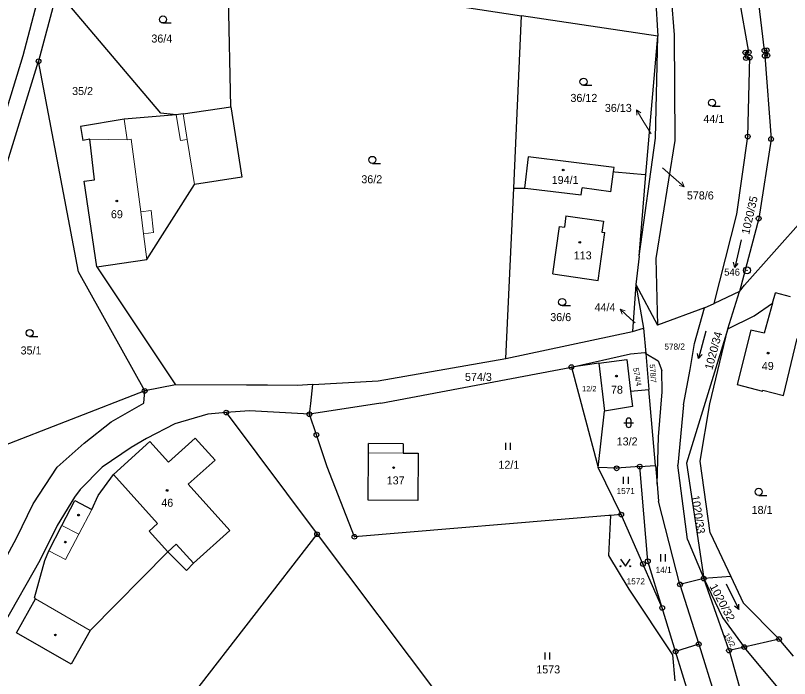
# Model space of a CAD drawing. Extents: x -601131 to -597152, y -1058536 to -1055911.
# Drawn here: x -599584.4 to -599420.5, y -1057555.3 to -1057414.9 of the extents above; entities that cross this region are included whole.
import ezdxf
from ezdxf.enums import TextEntityAlignment as Align

# ---------------------------------------------------------------- set-up
doc = ezdxf.new("R2010")
doc.units = 0
doc.header["$LTSCALE"] = 0.68
for name, color, linetype, lineweight in [('1', 7, 'Continuous', 25), ('3', 7, 'Continuous', 25), ('4', 7, 'Continuous', 13), ('5', 7, 'Continuous', 25), ('7', 7, 'Continuous', 13), ('8', 7, 'Continuous', 25)]:
    doc.layers.add(name, color=color, linetype=linetype, lineweight=lineweight)
doc.layers.add('2', color=7, linetype='Continuous')

msp = doc.modelspace()

# ---------------------------------------------------------------- linework, layer by layer
at = {"layer": '1'}
for p, q in [((-599429.13, -1057422.65), (-599435.94, -1057383.82)), ((-599576.56, -1057399.07), (-599582.83, -1057423.44)), ((-599425.81, -1057422.29), (-599427.99, -1057403.92)), ((-599539.45, -1057405.43), (-599477.25, -1057414.93)), ((-599538.83, -1057434.23), (-599539.45, -1057405.43)), ((-599575.56, -1057409.62), (-599579.52, -1057424.57)), ((-599445.63, -1057410.37), (-599444.9, -1057418.96)), ((-599553.62, -1057435.58), (-599574.11, -1057411.33)), ((-599448.9, -1057410.94), (-599448.41, -1057419.24)), ((-599478.88, -1057451.46), (-599477.25, -1057414.93)), ((-599448.41, -1057419.24), (-599477.25, -1057414.93)), ((-599444.9, -1057418.96), (-599444.76, -1057441.37)), ((-599450.89, -1057448.55), (-599448.41, -1057419.24)), ((-599448.85, -1057440.85), (-599448.41, -1057419.24)), ((-599425.81, -1057422.29), (-599425.32, -1057422.24)), ((-599425.32, -1057422.24), (-599425.2, -1057423.37)), ((-599582.83, -1057423.44), (-599589.35, -1057444.57)), ((-599429.73, -1057423.88), (-599428.91, -1057423.79)), ((-599429.33, -1057440.52), (-599428.91, -1057423.79)), ((-599425.2, -1057423.37), (-599425.73, -1057423.43)), ((-599425.73, -1057423.43), (-599424.4, -1057441.04)), ((-599586.09, -1057445.85), (-599579.52, -1057424.57)), ((-599571.05, -1057469.19), (-599579.52, -1057424.57)), ((-599548.9, -1057435.71), (-599538.83, -1057434.23)), ((-599538.83, -1057434.23), (-599536.5, -1057449.14)), ((-599561.39, -1057436.83), (-599570.64, -1057438.38)), ((-599550.36, -1057435.92), (-599561.39, -1057436.83)), ((-599550.36, -1057435.92), (-599553.62, -1057435.58)), ((-599548.9, -1057435.71), (-599550.36, -1057435.92)), ((-599570.64, -1057438.38), (-599570.15, -1057441.32)), ((-599568.65, -1057441.07), (-599570.15, -1057441.32)), ((-599567.7, -1057449.67), (-599568.65, -1057441.07)), ((-599452.36, -1057465.85), (-599448.85, -1057440.85)), ((-599444.76, -1057441.37), (-599448.83, -1057466.34)), ((-599431.65, -1057456.93), (-599429.33, -1057440.52)), ((-599424.4, -1057441.04), (-599427.03, -1057457.88)), ((-599475.87, -1057444.81), (-599476.59, -1057451.42)), ((-599457.64, -1057447.06), (-599475.87, -1057444.81)), ((-599458.34, -1057452.25), (-599457.76, -1057447.95)), ((-599457.76, -1057447.95), (-599457.64, -1057447.06)), ((-599457.76, -1057447.95), (-599457.48, -1057447.97)), ((-599457.48, -1057447.97), (-599451.11, -1057448.53)), ((-599451.11, -1057448.53), (-599450.89, -1057448.55)), ((-599569.89, -1057450), (-599567.7, -1057449.67)), ((-599567.16, -1057468.15), (-599569.89, -1057450)), ((-599536.5, -1057449.14), (-599546.51, -1057450.66)), ((-599452.36, -1057465.85), (-599450.89, -1057448.55)), ((-599556.6, -1057466.57), (-599546.51, -1057450.66)), ((-599480.54, -1057487.54), (-599478.88, -1057451.46)), ((-599478.88, -1057451.46), (-599476.59, -1057451.42)), ((-599476.59, -1057451.42), (-599476.45, -1057451.44)), ((-599476.45, -1057451.44), (-599464.64, -1057452.84)), ((-599464.64, -1057452.84), (-599464.44, -1057451.39)), ((-599458.34, -1057452.25), (-599464.44, -1057451.39)), ((-599467.88, -1057457.31), (-599468.17, -1057459.69)), ((-599467.88, -1057457.31), (-599459.91, -1057458.46)), ((-599436.45, -1057475.86), (-599431.65, -1057456.93)), ((-599427.03, -1057457.88), (-599431.06, -1057473.32)), ((-599430.01, -1057472.01), (-599417.49, -1057457.87)), ((-599470.62, -1057469.6), (-599469.2, -1057459.56)), ((-599469.2, -1057459.56), (-599468.17, -1057459.69)), ((-599459.91, -1057458.46), (-599460.23, -1057460.78)), ((-599461.02, -1057471.05), (-599459.64, -1057460.86)), ((-599460.23, -1057460.78), (-599459.64, -1057460.86)), ((-599448.83, -1057466.34), (-599448.42, -1057480.45)), ((-599567.16, -1057468.15), (-599556.6, -1057466.57)), ((-599567.16, -1057468.15), (-599550.49, -1057493.11)), ((-599557.05, -1057494.41), (-599571.05, -1057469.19)), ((-599470.62, -1057469.6), (-599461.02, -1057471.05)), ((-599453.06, -1057471.87), (-599453.74, -1057481.84)), ((-599453.06, -1057471.87), (-599451.39, -1057481.12)), ((-599431.06, -1057473.32), (-599430.01, -1057472.01)), ((-599431.06, -1057473.32), (-599436.45, -1057475.86)), ((-599433.54, -1057481.26), (-599431.06, -1057473.32)), ((-599424.11, -1057475.85), (-599423.48, -1057473.61)), ((-599420.32, -1057474.45), (-599423.48, -1057473.61)), ((-599438.48, -1057476.82), (-599436.45, -1057475.86)), ((-599427.95, -1057478.47), (-599424.11, -1057475.85)), ((-599424.11, -1057475.85), (-599425.87, -1057482.14)), ((-599438.48, -1057476.82), (-599448.42, -1057480.45)), ((-599440.6, -1057484.39), (-599438.48, -1057476.82)), ((-599433.54, -1057481.26), (-599427.95, -1057478.47)), ((-599453.74, -1057481.84), (-599451.39, -1057481.12)), ((-599451.39, -1057481.12), (-599450.93, -1057486.45)), ((-599433.54, -1057481.26), (-599442.33, -1057509.73)), ((-599437.38, -1057497.13), (-599433.54, -1057481.26)), ((-599480.54, -1057487.54), (-599453.74, -1057481.84)), ((-599428.67, -1057481.52), (-599431.56, -1057493.06)), ((-599425.87, -1057482.14), (-599428.67, -1057481.52)), ((-599441.54, -1057489.85), (-599440.6, -1057484.39)), ((-599421.79, -1057495.35), (-599418.87, -1057483.31)), ((-599507.58, -1057492.26), (-599480.54, -1057487.54)), ((-599466.67, -1057489.35), (-599454.15, -1057486.55)), ((-599460.87, -1057488.55), (-599454.95, -1057487.73)), ((-599454.95, -1057487.73), (-599454.15, -1057494.47)), ((-599450.93, -1057486.45), (-599448.33, -1057488.07)), ((-599450.93, -1057486.45), (-599450.28, -1057494.08)), ((-599507.04, -1057497.01), (-599466.67, -1057489.35)), ((-599460.87, -1057488.55), (-599466.67, -1057489.35)), ((-599466.67, -1057489.35), (-599461.02, -1057510.61)), ((-599460.87, -1057488.55), (-599459.71, -1057498.67)), ((-599448.33, -1057488.07), (-599447.53, -1057490.08)), ((-599447.48, -1057494.57), (-599447.53, -1057490.08)), ((-599442.92, -1057497.38), (-599441.54, -1057489.85)), ((-599521.47, -1057493.07), (-599507.58, -1057492.26)), ((-599557.05, -1057494.41), (-599595.76, -1057509.42)), ((-599557.26, -1057497.01), (-599557.05, -1057494.41)), ((-599550.49, -1057493.11), (-599557.05, -1057494.41)), ((-599535.5, -1057493.2), (-599550.49, -1057493.11)), ((-599531.04, -1057493.21), (-599535.5, -1057493.2)), ((-599524.78, -1057493.23), (-599531.04, -1057493.21)), ((-599521.47, -1057493.07), (-599524.78, -1057493.23)), ((-599521.9, -1057497.05), (-599521.47, -1057493.07)), ((-599454.15, -1057494.47), (-599450.28, -1057494.08)), ((-599448.88, -1057510.19), (-599450.28, -1057494.08)), ((-599431.56, -1057493.06), (-599426.19, -1057494.46)), ((-599426.19, -1057494.46), (-599426.15, -1057494.28)), ((-599426.15, -1057494.28), (-599421.79, -1057495.35)), ((-599454.15, -1057494.47), (-599453.76, -1057497.74)), ((-599448.25, -1057504.11), (-599447.48, -1057494.57)), ((-599564.18, -1057500.99), (-599557.26, -1057497.01)), ((-599507.04, -1057497.01), (-599522.15, -1057499.34)), ((-599522.15, -1057499.34), (-599521.9, -1057497.05)), ((-599442.92, -1057497.38), (-599444.18, -1057510.12)), ((-599439.43, -1057509.3), (-599437.38, -1057497.13)), ((-599539.77, -1057498.99), (-599543.66, -1057499.37)), ((-599534.83, -1057498.6), (-599539.77, -1057498.99)), ((-599539.77, -1057498.99), (-599520.55, -1057524.78)), ((-599522.15, -1057499.34), (-599534.83, -1057498.6)), ((-599520.67, -1057503.74), (-599522.15, -1057499.34)), ((-599461.02, -1057510.61), (-599459.71, -1057498.67)), ((-599453.76, -1057497.74), (-599459.71, -1057498.67)), ((-599543.66, -1057499.37), (-599550.67, -1057501.4)), ((-599569.89, -1057505.48), (-599564.18, -1057500.99)), ((-599550.67, -1057501.4), (-599556.64, -1057504.51)), ((-599518.39, -1057510.52), (-599520.67, -1057503.74)), ((-599448.53, -1057514.19), (-599448.25, -1057504.11)), ((-599575.55, -1057510.53), (-599569.89, -1057505.48)), ((-599563.66, -1057512.09), (-599555.97, -1057505.14)), ((-599556.64, -1057504.51), (-599559.92, -1057506.43)), ((-599555.97, -1057505.14), (-599552, -1057509.51)), ((-599552, -1057509.51), (-599546.33, -1057504.4)), ((-599546.33, -1057504.4), (-599542.14, -1057509.05)), ((-599509.68, -1057507.53), (-599509.67, -1057505.53)), ((-599502.28, -1057505.61), (-599509.67, -1057505.53)), ((-599502.28, -1057505.61), (-599502.28, -1057507.57)), ((-599559.92, -1057506.43), (-599566.02, -1057510.55)), ((-599509.71, -1057517.59), (-599509.68, -1057507.53)), ((-599542.14, -1057509.05), (-599547.84, -1057514.18)), ((-599502.28, -1057507.57), (-599499.16, -1057507.57)), ((-599499.16, -1057507.57), (-599499.2, -1057517.63)), ((-599580.69, -1057518.33), (-599575.55, -1057510.53)), ((-599566.02, -1057510.55), (-599570.69, -1057515.28)), ((-599512.64, -1057525.32), (-599518.39, -1057510.52)), ((-599456.13, -1057520.62), (-599461.02, -1057510.61)), ((-599457.11, -1057510.81), (-599461.02, -1057510.61)), ((-599452.21, -1057510.44), (-599457.11, -1057510.81)), ((-599452.21, -1057510.44), (-599448.88, -1057510.19)), ((-599450.5, -1057530.51), (-599452.21, -1057510.44)), ((-599448.88, -1057510.19), (-599448.53, -1057514.19)), ((-599442.11, -1057525.88), (-599444.18, -1057510.12)), ((-599442.33, -1057509.73), (-599438.67, -1057534.18)), ((-599437.27, -1057524.48), (-599439.43, -1057509.3)), ((-599566.93, -1057516.54), (-599563.66, -1057512.09)), ((-599570.69, -1057515.28), (-599571.92, -1057516.93)), ((-599547.84, -1057514.18), (-599539.01, -1057524)), ((-599448.53, -1057514.19), (-599448.22, -1057517.77)), ((-599571.92, -1057516.93), (-599575.59, -1057522.91)), ((-599568.24, -1057519.52), (-599566.93, -1057516.54)), ((-599584.18, -1057525.58), (-599580.69, -1057518.33)), ((-599574.6, -1057522.94), (-599571.84, -1057517.6)), ((-599571.84, -1057517.6), (-599568.24, -1057519.52)), ((-599499.2, -1057517.63), (-599509.71, -1057517.59)), ((-599443.69, -1057535.4), (-599448.22, -1057517.77)), ((-599456.13, -1057520.62), (-599458.43, -1057520.81)), ((-599451.54, -1057531.08), (-599456.13, -1057520.62)), ((-599458.78, -1057520.84), (-599512.64, -1057525.32)), ((-599458.43, -1057520.81), (-599458.8, -1057529.28)), ((-599458.43, -1057520.81), (-599458.78, -1057520.84)), ((-599575.59, -1057522.91), (-599579.25, -1057530.31)), ((-599577.37, -1057528.29), (-599574.6, -1057522.94)), ((-599568.17, -1057586.29), (-599520.55, -1057524.78)), ((-599539.01, -1057524), (-599546.7, -1057530.92)), ((-599520.55, -1057524.78), (-599475.21, -1057585.02)), ((-599437.27, -1057524.48), (-599432.94, -1057533.76)), ((-599592.18, -1057540.3), (-599584.18, -1057525.58)), ((-599442.11, -1057525.88), (-599438.67, -1057534.18)), ((-599578.22, -1057530.31), (-599577.37, -1057528.29)), ((-599552.12, -1057528.49), (-599568.62, -1057545.16)), ((-599548.17, -1057532.47), (-599552.12, -1057528.49)), ((-599579.25, -1057530.31), (-599586.95, -1057543.9)), ((-599580.4, -1057538.26), (-599578.22, -1057530.31)), ((-599458.8, -1057529.28), (-599454.54, -1057536.41)), ((-599546.7, -1057530.92), (-599548.17, -1057532.47)), ((-599447.46, -1057540.37), (-599451.54, -1057531.08)), ((-599447.46, -1057540.37), (-599450.5, -1057530.51)), ((-599432.94, -1057533.76), (-599438.67, -1057534.18)), ((-599432.94, -1057533.76), (-599430.34, -1057539.31)), ((-599441.18, -1057534.8), (-599443.69, -1057535.4)), ((-599443.69, -1057535.4), (-599439.72, -1057548.06)), ((-599438.67, -1057534.18), (-599441.18, -1057534.8)), ((-599438.67, -1057534.18), (-599434.67, -1057542.4)), ((-599433.31, -1057549.41), (-599438.67, -1057534.18)), ((-599454.54, -1057536.41), (-599445.3, -1057550.3)), ((-599584.21, -1057545.64), (-599580.15, -1057538.44)), ((-599580.15, -1057538.44), (-599580.4, -1057538.26)), ((-599430.34, -1057539.31), (-599422.72, -1057547)), ((-599434.67, -1057542.4), (-599430.08, -1057548.68)), ((-599568.62, -1057545.16), (-599572.64, -1057552.3)), ((-599572.64, -1057552.3), (-599584.21, -1057545.64)), ((-599439.72, -1057548.06), (-599430.15, -1057578.59)), ((-599422.72, -1057547), (-599430.08, -1057548.68)), ((-599419.62, -1057550.58), (-599422.72, -1057547)), ((-599440.66, -1057562.39), (-599444.61, -1057549.59)), ((-599430.08, -1057548.68), (-599433.31, -1057549.41)), ((-599433.31, -1057549.41), (-599425.07, -1057578.4)), ((-599422.52, -1057557.74), (-599430.08, -1057548.68)), ((-599445.3, -1057550.3), (-599444.79, -1057555.84))]:
    msp.add_line(p, q, dxfattribs=at)
for points in [[(-599429.73, -1057423.88), (-599429.85, -1057422.73), (-599429.13, -1057422.65)], [(-599452.36, -1057465.85), (-599453.06, -1057471.87), (-599448.42, -1057480.45)], [(-599454.15, -1057486.55), (-599451.15, -1057486.25), (-599450.93, -1057486.45)], [(-599439.72, -1057548.06), (-599444.61, -1057549.59), (-599447.46, -1057540.37)]]:
    msp.add_lwpolyline(points, dxfattribs=at)
at = {"layer": '3'}
for p, q in [((-599553.173, -1057416.45), (-599551.423, -1057416.45)), ((-599464.123, -1057429.66), (-599462.373, -1057429.66)), ((-599436.913, -1057434.1), (-599435.163, -1057434.1)), ((-599508.833, -1057446.21), (-599507.083, -1057446.21)), ((-599432.097, -1057468.228), (-599432.366, -1057467.163)), ((-599468.643, -1057476.34), (-599466.893, -1057476.34)), ((-599581.413, -1057482.89), (-599579.663, -1057482.89)), ((-599439.749, -1057487.542), (-599439.981, -1057486.468)), ((-599455.061, -1057500.651), (-599455.061, -1057501.652)), ((-599454.059, -1057501.652), (-599454.059, -1057500.651)), ((-599455.561, -1057501.151), (-599453.559, -1057501.151)), ((-599480.591, -1057506.91), (-599480.591, -1057505.41)), ((-599479.59, -1057506.91), (-599479.59, -1057505.41)), ((-599455.621, -1057514.12), (-599455.621, -1057512.62)), ((-599454.62, -1057514.12), (-599454.62, -1057512.62)), ((-599427.023, -1057516.54), (-599425.273, -1057516.54)), ((-599447.731, -1057530.53), (-599447.731, -1057529.03)), ((-599446.73, -1057530.53), (-599446.73, -1057529.03)), ((-599431.265, -1057540.706), (-599432.144, -1057540.047)), ((-599472.231, -1057551.32), (-599472.231, -1057549.82)), ((-599471.23, -1057551.32), (-599471.23, -1057549.82))]:
    msp.add_line(p, q, dxfattribs=at)
for points in [[(-599430.747, -1057462.382), (-599432.097, -1057468.228), (-599431.389, -1057467.389)], [(-599438.196, -1057481.747), (-599439.749, -1057487.542), (-599439.012, -1057486.728)], [(-599456.26, -1057530.049), (-599455.26, -1057531.55), (-599454.26, -1057530.049)], [(-599433.895, -1057535.313), (-599431.265, -1057540.706), (-599431.243, -1057539.607)]]:
    msp.add_lwpolyline(points, dxfattribs=at)
for centre, radius in [((-599553.1729, -1057415.6998), 0.75), ((-599464.1229, -1057428.9098), 0.75), ((-599436.9129, -1057433.3498), 0.75), ((-599508.8329, -1057445.4598), 0.75), ((-599468.6429, -1057475.5898), 0.75), ((-599581.4129, -1057482.1398), 0.75), ((-599427.0229, -1057515.7898), 0.75), ((-599456.26, -1057531.5495), 0.1), ((-599454.26, -1057531.5495), 0.1)]:
    msp.add_circle(centre, radius, dxfattribs=at)
for centre, start, end in [((-599454.56, -1057500.6509), 0, 180), ((-599454.56, -1057501.6509), 180, 359.98789)]:
    msp.add_arc(centre, 0.5, start, end, dxfattribs=at)
at = {"layer": '4'}
for p, q in [((-599561.39, -1057436.83), (-599560.79, -1057441.19)), ((-599548.9, -1057435.71), (-599548.03, -1057441.14)), ((-599568.65, -1057441.07), (-599560.79, -1057441.19)), ((-599560.79, -1057441.19), (-599559.91, -1057441.07)), ((-599559.91, -1057441.07), (-599557.85, -1057456.44)), ((-599546.51, -1057450.66), (-599548.03, -1057441.14)), ((-599557.85, -1057456.44), (-599555.65, -1057456.15)), ((-599557.85, -1057456.44), (-599557.31, -1057461.12)), ((-599555.65, -1057456.15), (-599555.15, -1057460.84)), ((-599557.31, -1057461.12), (-599555.15, -1057460.84)), ((-599556.6, -1057466.57), (-599557.31, -1057461.12)), ((-599502.28, -1057507.57), (-599509.68, -1057507.53)), ((-599568.24, -1057519.52), (-599571.01, -1057524.79)), ((-599574.6, -1057522.94), (-599571.01, -1057524.79)), ((-599571.01, -1057524.79), (-599573.82, -1057530.15)), ((-599552.12, -1057528.49), (-599556.08, -1057524.14)), ((-599550.38, -1057526.87), (-599552.12, -1057528.49)), ((-599546.7, -1057530.92), (-599550.38, -1057526.87)), ((-599573.82, -1057530.15), (-599577.37, -1057528.29)), ((-599580.15, -1057538.44), (-599568.62, -1057545.16))]:
    msp.add_line(p, q, dxfattribs=at)
for points in [[(-599550.36, -1057435.92), (-599549.46, -1057441.37), (-599548.03, -1057441.14)], [(-599556.08, -1057524.14), (-599554.33, -1057522.48), (-599563.66, -1057512.09)]]:
    msp.add_lwpolyline(points, dxfattribs=at)
at = {"layer": '5'}
for centre in [(-599468.4168, -1057447.6092), (-599562.9468, -1057454.1592), (-599464.9068, -1057462.9192), (-599425.0268, -1057486.4092), (-599457.1468, -1057491.2692), (-599504.3368, -1057510.6692), (-599552.2968, -1057515.4992), (-599571.0468, -1057520.7192), (-599573.8568, -1057526.4392), (-599575.9668, -1057546.1092)]:
    msp.add_circle(centre, 0.175, dxfattribs=at)
at = {"layer": '7'}
for p, q in [((-599452.896, -1057434.868), (-599452.809, -1057435.984)), ((-599442.785, -1057451.149), (-599443.212, -1057450.114)), ((-599456.37, -1057477.112), (-599455.961, -1057478.154))]:
    msp.add_line(p, q, dxfattribs=at)
for points in [[(-599449.83, -1057439.95), (-599451.35, -1057437.44), (-599452.896, -1057434.868), (-599451.951, -1057435.468)], [(-599447.4, -1057447.11), (-599445.05, -1057449.18), (-599442.785, -1057451.149), (-599443.869, -1057450.87)], [(-599453.15, -1057480.02), (-599454.14, -1057479.12), (-599456.37, -1057477.112), (-599455.291, -1057477.41)]]:
    msp.add_lwpolyline(points, dxfattribs=at)
at = {"layer": '8'}
for centre, radius in [((-599429.85, -1057422.7299), 0.5), ((-599429.13, -1057422.6499), 0.5), ((-599425.81, -1057422.2899), 0.5), ((-599425.81, -1057422.2899), 0.0303), ((-599425.32, -1057422.2399), 0.5), ((-599425.32, -1057422.2399), 0.0303), ((-599429.73, -1057423.8799), 0.5), ((-599429.85, -1057422.7299), 0.0303), ((-599429.73, -1057423.8799), 0.0303), ((-599428.91, -1057423.7899), 0.5), ((-599429.13, -1057422.6499), 0.0303), ((-599428.91, -1057423.7899), 0.0303), ((-599425.73, -1057423.4299), 0.5), ((-599425.73, -1057423.4299), 0.0303), ((-599425.2, -1057423.3699), 0.5), ((-599425.2, -1057423.3699), 0.0303), ((-599579.52, -1057424.5699), 0.5), ((-599579.52, -1057424.5699), 0.0303), ((-599429.33, -1057440.5199), 0.5), ((-599429.33, -1057440.5199), 0.0303), ((-599424.4, -1057441.0399), 0.5), ((-599424.4, -1057441.0399), 0.0303), ((-599427.03, -1057457.8799), 0.5), ((-599427.03, -1057457.8799), 0.0303), ((-599429.49, -1057468.8698), 0.75), ((-599429.49, -1057468.8698), 0.03), ((-599466.67, -1057489.3499), 0.5), ((-599466.67, -1057489.3499), 0.0303), ((-599557.05, -1057494.4099), 0.5), ((-599557.05, -1057494.4099), 0.0303), ((-599539.77, -1057498.9899), 0.5), ((-599539.77, -1057498.9899), 0.0303), ((-599522.15, -1057499.3399), 0.5), ((-599522.15, -1057499.3399), 0.0303), ((-599520.67, -1057503.7399), 0.5), ((-599520.67, -1057503.7399), 0.0303), ((-599457.11, -1057510.8099), 0.5), ((-599457.11, -1057510.8099), 0.0303), ((-599452.21, -1057510.4399), 0.5), ((-599452.21, -1057510.4399), 0.0303), ((-599456.13, -1057520.6199), 0.5), ((-599456.13, -1057520.6199), 0.0303), ((-599520.55, -1057524.7799), 0.5), ((-599520.55, -1057524.7799), 0.0303), ((-599512.64, -1057525.3199), 0.5), ((-599512.64, -1057525.3199), 0.0303), ((-599450.5, -1057530.5099), 0.5), ((-599450.5, -1057530.5099), 0.0303), ((-599451.54, -1057531.0799), 0.5), ((-599451.54, -1057531.0799), 0.0303), ((-599438.67, -1057534.1799), 0.5), ((-599443.69, -1057535.3999), 0.5), ((-599443.69, -1057535.3999), 0.0303), ((-599438.67, -1057534.1799), 0.0303), ((-599447.46, -1057540.3699), 0.5), ((-599447.46, -1057540.3699), 0.0303), ((-599422.72, -1057546.9999), 0.5), ((-599439.72, -1057548.0599), 0.5), ((-599439.72, -1057548.0599), 0.0303), ((-599430.08, -1057548.6799), 0.5), ((-599422.72, -1057546.9999), 0.0303), ((-599444.61, -1057549.5899), 0.5), ((-599444.61, -1057549.5899), 0.0303), ((-599433.31, -1057549.4099), 0.5), ((-599433.31, -1057549.4099), 0.0303), ((-599430.08, -1057548.6799), 0.0303)]:
    msp.add_circle(centre, radius, dxfattribs=at)

# ---------------------------------------------------------------- texts
at = {"layer": '2'}
for s, height, p in [('36/4', 1.7, (-599555.63, -1057420.604)), ('35/2', 1.7, (-599572.42, -1057431.725)), ('36/12', 1.7, (-599466.89, -1057433.185)), ('44/1', 1.7, (-599438.73, -1057437.625)), ('36/2', 1.7, (-599511.17, -1057450.415)), ('194/1', 1.7, (-599470.86, -1057450.564)), ('69', 1.7, (-599564.2, -1057457.824)), ('113', 1.7, (-599466.19, -1057466.545)), ('36/6', 1.7, (-599471.16, -1057479.625)), ('35/1', 1.7, (-599583.33, -1057486.685)), ('49', 1.7, (-599426.37, -1057489.975)), ('574/3', 1.7, (-599489.22, -1057492.295)), ('12/2', 1.14, (-599464.44, -1057494.515)), ('78', 1.7, (-599458.31, -1057494.995)), ('13/2', 1.7, (-599457.1, -1057505.955)), ('12/1', 1.7, (-599482.14, -1057510.905)), ('137', 1.7, (-599505.8, -1057514.215)), ('18/1', 1.7, (-599428.52, -1057520.475))]:
    msp.add_text(s, height=height, dxfattribs=at).set_placement(p)
for s, p in [('36/13', (-599453.91, -1057435.304)), ('44/4', (-599457.359, -1057477.535))]:
    msp.add_text(s, height=1.7, dxfattribs=at).set_placement(p, align=Align.RIGHT)
for s, height, p in [('578/6', 1.7, (-599439.39, -1057453.844)), ('578/2', 1.3, (-599444.819, -1057485.665)), ('1571', 1.3, (-599455.179, -1057516.265)), ('46', 1.7, (-599552.269, -1057518.952)), ('14/1', 1.3, (-599447.149, -1057532.974)), ('1572', 1.3, (-599453.049, -1057535.395)), ('1573', 1.7, (-599471.6, -1057554.262))]:
    msp.add_text(s, height=height, dxfattribs=at).set_placement(p, align=Align.CENTER)
for s, height, rotation, p in [('1020/35', 1.7, 77, (-599429.055, -1057461.375)), ('1020/34', 1.7, 75, (-599436.849, -1057490.059)), ('578/7', 1.139, 274, (-599450.124, -1057488.799)), ('1020/33', 1.7, 279, (-599441.309, -1057516.656))]:
    msp.add_text(s, height=height, rotation=rotation, dxfattribs=at).set_placement(p)
msp.add_text('574/4', height=1.139, rotation=280, dxfattribs=at).set_placement((-599453.2812, -1057491.5196), align=Align.CENTER)
at = {"layer": '2', "width": 1.05}
for s, height, rotation, p in [('1020/32', 1.7, 298, (-599437.495, -1057535.809)), ('15/2', 1.14, 299, (-599434.389, -1057546.078))]:
    msp.add_text(s, height=height, rotation=rotation, dxfattribs=at).set_placement(p)
at = {"layer": '8'}
msp.add_text('546', height=1.5, dxfattribs=at).set_placement((-599430.989, -1057469.987), align=Align.RIGHT)

doc.saveas('drawing.dxf')
